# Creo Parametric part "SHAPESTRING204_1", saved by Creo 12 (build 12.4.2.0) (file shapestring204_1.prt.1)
Units: Custom; MM, KILOGRAM, SECS

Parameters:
  PTC_WM_ITERATION = "0"
  PTC_WM_VERSION = "-.0"
  PTC_WM_LIFECYCLE_STATE = "In Work"
  PTC_WM_LIFECYCLE = "MO_CADDocument"
  PTC_WM_CREATED_BY = "Maximilian Roepper (Z0017RMS: MO)"
  PTC_WM_CREATED_ON = "18-Sep-26 11:36:42 AM"
  PTC_WM_MODIFIED_BY = "Maximilian Roepper (Z0017RMS: MO)"
  PTC_WM_MODIFIED_ON = "18-Sep-26 11:36:46 AM"
  PDMLINKNUMBER = "PDM000071455321"
  PTC_WM_NAME = "shapestring204_1.prt"
  PTC_WM_NUMBER = "PDM000071455321"

Other parameters: WEIGHT, WEIGHT_FACTOR, WEIGHT_ADD, _MASS_TEMP, _DIFF_TEMP, MC_ERRORS, SUPPLIER

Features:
  1. coordinate system
  2. datum plane "PRT_YZ"
  3. datum plane "PRT_XY"
  4. datum plane "PRT_XZ"
  5. coordinate system
  6. datum axis
  7. datum axis
  8. datum axis
  9. coordinate system
  10. imported feature

Other named items: PRT, SIEMENS_MO, DRW_VIEW_ORG, PRT_X, PRT_Y, PRT_Z, CS0, ROUGH_GROB

Layers: 00_STD_CSYS-KSYS, 01_STD_PLANES-EBENEN, 02_STD_AXES-ACHSEN, 03_STD_CSYS-KSYS, 24_IMPORT_FEAT-IMPORT_KE, INTFCLR

Surfaces: 1 plane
